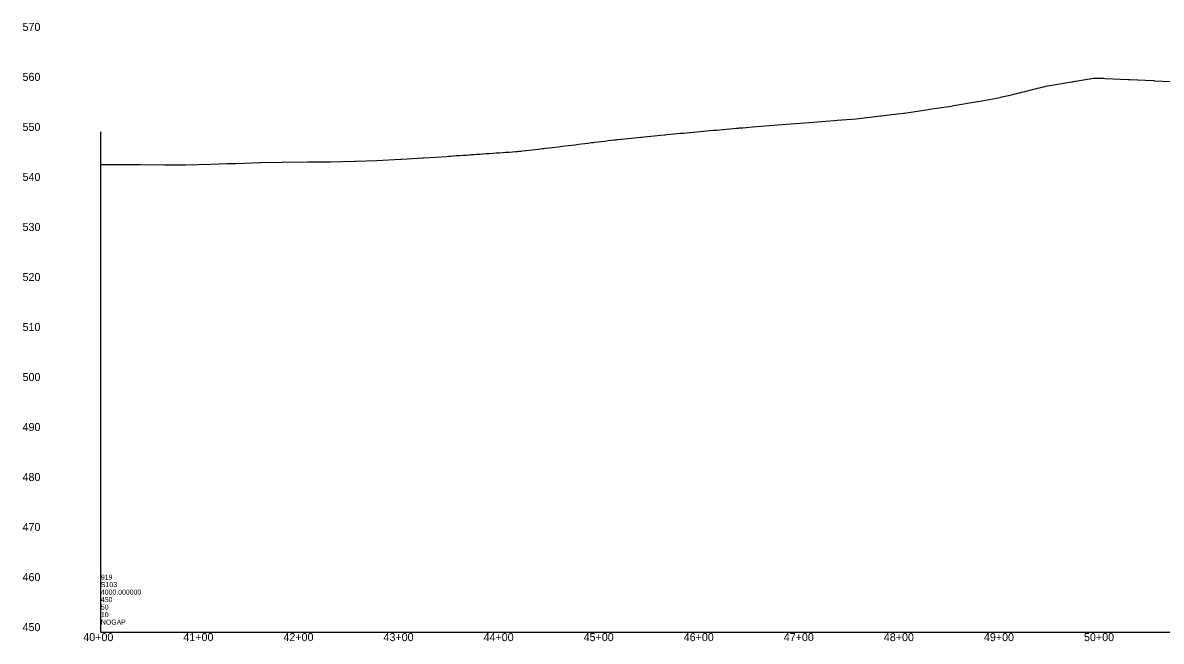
# Model space of a CAD drawing. Extents: x 49922 to 54713, y 49991 to 62800.
# Drawn here: x 49922 to 51060, y 49991 to 50609 of the extents above; entities that cross this region are included whole.
import ezdxf

# ---------------------------------------------------------------- set-up
doc = ezdxf.new("R2010")
doc.units = 0
for name, color, linetype in [('RD_DDB_ElevTX', 7, 'Continuous'), ('RD_DDB_Profile_EX', 7, 'Continuous'), ('RD_DDB_StaTX', 7, 'Continuous'), ('RD_GPK_Profile_Cell', 7, 'Continuous')]:
    doc.layers.add(name, color=color, linetype=linetype)

msp = doc.modelspace()

# ---------------------------------------------------------------- linework, layer by layer
at = {"layer": 'RD_DDB_Profile_EX'}
for points in [[(50546.2, 50495.4), (50549.5, 50495.8), (50552.8, 50496.1), (50556.1, 50496.4), (50559.3, 50496.7), (50563.1, 50497.1), (50564, 50497.2), (50565.9, 50497.3), (50569.2, 50497.7), (50572.5, 50498), (50575.8, 50498.3), (50579.1, 50498.6), (50582.3, 50498.9), (50585.6, 50499.2), (50588.2, 50499.4), (50588.9, 50499.5), (50592.2, 50499.8), (50595.5, 50500.1), (50598.8, 50500.4), (50602.1, 50500.7), (50605.4, 50501), (50608.6, 50501.3), (50612.1, 50501.6), (50612.6, 50501.6), (50615.2, 50501.9), (50618.5, 50502.2), (50621.8, 50502.5), (50625.2, 50502.8), (50628.4, 50503.1), (50631.7, 50503.4), (50634.9, 50503.7), (50637.3, 50503.9), (50638.2, 50504), (50641.5, 50504.2), (50644.8, 50504.5), (50651.3, 50505.1), (50659.8, 50505.8), (50684.8, 50507.7), (50707.8, 50509.5), (50732.8, 50511.5), (50735.7, 50511.7), (50754.8, 50513.2), (50779.1, 50516), (50779.8, 50516.1), (50801.9, 50518.7), (50803, 50518.9), (50826.6, 50522.4), (50828.1, 50522.6), (50849.7, 50525.8), (50850.9, 50526), (50852.4, 50526.3), (50875.9, 50530.4), (50876.6, 50530.5), (50898.5, 50534.4), (50899.1, 50534.6), (50910.1, 50537.2), (50912.1, 50537.7), (50914.1, 50538.1), (50916.1, 50538.6), (50918.1, 50539.1), (50920.1, 50539.6), (50922.1, 50540.1), (50923.5, 50540.4), (50924.1, 50540.6), (50926.4, 50541.2), (50928.1, 50541.6), (50930.1, 50542.1), (50932.1, 50542.6), (50934.1, 50543.1), (50936.1, 50543.6), (50938.1, 50544.1), (50940.1, 50544.6), (50942.1, 50545.1), (50944.1, 50545.7), (50946.1, 50546.2), (50948.1, 50546.5), (50950.1, 50546.9), (50952.1, 50547.2), (50954.1, 50547.5), (50956.1, 50547.8), (50958.1, 50548.1), (50960.1, 50548.5), (50962, 50548.8), (50964, 50549.1), (50966, 50549.4), (50968, 50549.7), (50970, 50550.1), (50970.9, 50550.2), (50972, 50550.4), (50974, 50550.7), (50976, 50551), (50978, 50551.3), (50980, 50551.7), (50982, 50552), (50984, 50552.3), (50986, 50552.6), (50988, 50553), (50988.5, 50553), (50990, 50553.3), (50992, 50553.7), (50992.4, 50553.8)], [(50992.4, 50553.8), (50994, 50553.8), (50996, 50553.8), (50998, 50553.8), (51000, 50553.7), (51001.2, 50553.7), (51002.3, 50553.6), (51003.5, 50553.5), (51026.4, 50552.5), (51028.2, 50552.4), (51051.7, 50551.3), (51052.9, 50551.2), (51077.1, 50550.1)], [(50000, 50467.6), (50013.9, 50467.5), (50014.6, 50467.5), (50038.9, 50467.3), (50039.6, 50467.3), (50063.9, 50467.1), (50084.2, 50467), (50084.6, 50467), (50109.6, 50467.8), (50126.3, 50468.3), (50134.7, 50468.5), (50159.6, 50469.3), (50160, 50469.3), (50181.3, 50469.9), (50181.9, 50469.9), (50206.3, 50470), (50207, 50470), (50228.9, 50470.1), (50229.9, 50470.1), (50253.9, 50470.9), (50254.9, 50470.9), (50275.6, 50471.5), (50299.4, 50472.9), (50300.6, 50472.9), (50321.7, 50474.1), (50322.7, 50474.1), (50345.8, 50475.6), (50347.7, 50475.8), (50349, 50475.8), (50352.3, 50476.1), (50355.5, 50476.3), (50358.8, 50476.5), (50362.1, 50476.7), (50365.4, 50476.9), (50368, 50477.1), (50368.7, 50477.2), (50370.1, 50477.3), (50372, 50477.4), (50372.5, 50477.5), (50375.3, 50477.7), (50378.6, 50477.9), (50381.8, 50478.1), (50385.1, 50478.3), (50388.4, 50478.5), (50391.7, 50478.8), (50395.1, 50479), (50398.3, 50479.2), (50401.6, 50479.4), (50404.8, 50479.7), (50408.1, 50479.9), (50411.4, 50480.1), (50414.7, 50480.4), (50416.3, 50480.5), (50418, 50480.6), (50419.5, 50480.8), (50421.3, 50481), (50424.6, 50481.4), (50427.9, 50481.8), (50431.1, 50482.1), (50434.4, 50482.5), (50437.7, 50482.9), (50441, 50483.3), (50442.9, 50483.5), (50444.3, 50483.7), (50447.6, 50484), (50450.9, 50484.4), (50454.2, 50484.8), (50457.4, 50485.2), (50460.7, 50485.6), (50464, 50486), (50467.3, 50486.4), (50470.6, 50486.8), (50473.9, 50487.2), (50477.2, 50487.6), (50480.4, 50488), (50483.7, 50488.5), (50486.5, 50488.8), (50487, 50488.9), (50490.3, 50489.3), (50492.3, 50489.5), (50493.6, 50489.7), (50496.9, 50490.1), (50500.2, 50490.5), (50503.5, 50490.9), (50506.7, 50491.3), (50510, 50491.7), (50513.3, 50492.1), (50514.2, 50492.2), (50515.7, 50492.4), (50516.6, 50492.5), (50519.9, 50492.8), (50523.2, 50493.1), (50526.5, 50493.5), (50529.8, 50493.8), (50533, 50494.1), (50536.3, 50494.5), (50539.6, 50494.8), (50540.3, 50494.9), (50540.9, 50494.9), (50542.9, 50495.1), (50546.2, 50495.4)]]:
    msp.add_lwpolyline(points, dxfattribs=at)
at = {"layer": 'RD_GPK_Profile_Cell'}
for q in [(50000, 50500), (54600, 50000), (50000, 50000)]:
    msp.add_line((50000, 50000), q, dxfattribs=at)

# ---------------------------------------------------------------- texts
at = {"layer": 'RD_DDB_ElevTX'}
for s, p in [('570', (49921.7, 50601)), ('560', (49921.7, 50551)), ('550', (49921.7, 50501)), ('540', (49921.7, 50451)), ('530', (49921.7, 50401)), ('520', (49921.7, 50351)), ('510', (49921.7, 50301)), ('500', (49921.7, 50251)), ('490', (49921.7, 50201)), ('480', (49921.7, 50151)), ('470', (49921.7, 50101)), ('460', (49921.7, 50051)), ('450', (49921.7, 50001))]:
    msp.add_text(s, height=8, dxfattribs=at).set_placement(p)
at = {"layer": 'RD_DDB_StaTX'}
for s, p in [('40+00', (49982.4, 49991)), ('41+00', (50082.4, 49991)), ('42+00', (50182.4, 49991)), ('43+00', (50282.4, 49991)), ('44+00', (50382.4, 49991)), ('45+00', (50482.4, 49991)), ('46+00', (50582.4, 49991)), ('47+00', (50682.4, 49991)), ('48+00', (50782.4, 49991)), ('49+00', (50882.4, 49991)), ('50+00', (50982.4, 49991))]:
    msp.add_text(s, height=8, dxfattribs=at).set_placement(p)
at = {"layer": 'RD_GPK_Profile_Cell'}
for s, p in [('919', (50000, 50052.5)), ('S103', (50000, 50045)), ('4000.000000', (50000, 50037.5)), ('450', (50000, 50030)), ('50', (50000, 50022.5)), ('10', (50000, 50015)), ('NOGAP', (50000, 50007.5))]:
    msp.add_text(s, height=5, dxfattribs=at).set_placement(p)

doc.saveas('drawing.dxf')
